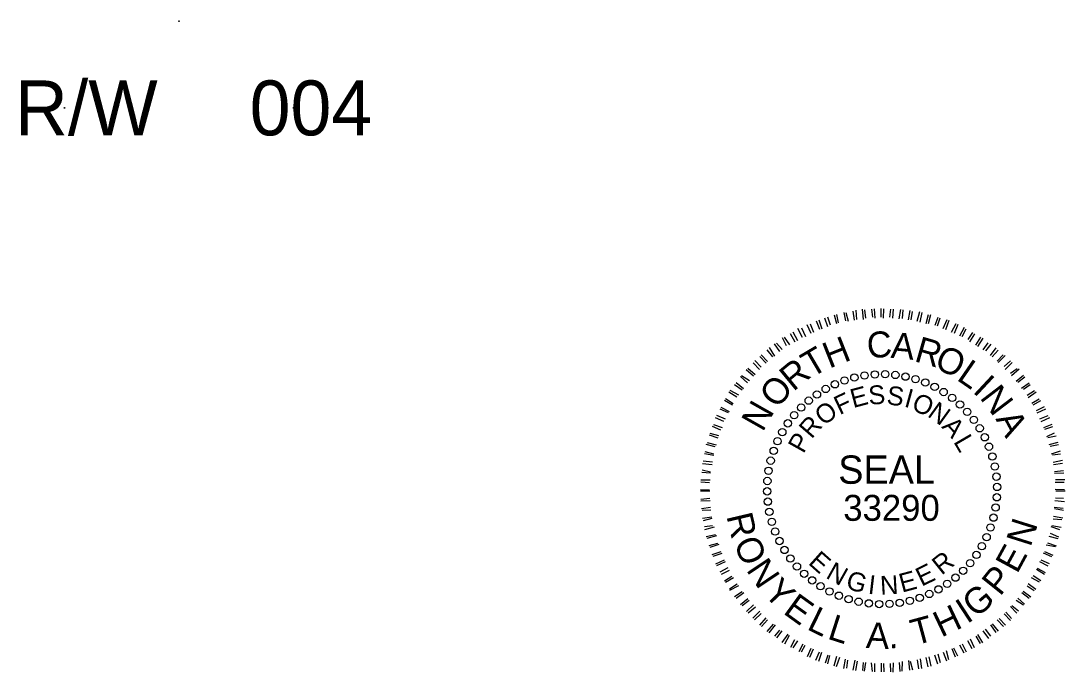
# Model space of a CAD drawing. Extents: x -0.56 to 3.44, y 0 to 1.83.
# Drawn here: x 2.925 to 3.3052, y 1.5473 to 1.7845 of the extents above; entities that cross this region are included whole.
import ezdxf

# ---------------------------------------------------------------- set-up
doc = ezdxf.new("R2010")
doc.units = 0
doc.layers.add('Sheet PE Seal Cell', color=7, linetype='Continuous')
doc.layers.add('Sheet_Title_Block_Text', color=7, linetype='Continuous')

msp = doc.modelspace()

# ---------------------------------------------------------------- linework, layer by layer
at = {"layer": 'Sheet PE Seal Cell'}
for p, q in [((3.21875, 1.67664), (3.21971, 1.67371)), ((3.2221, 1.67407), (3.22124, 1.67723)), ((3.22191, 1.6775), (3.22254, 1.67443)), ((3.22537, 1.67516), (3.22474, 1.67823)), ((3.22532, 1.67826), (3.22618, 1.67509)), ((3.22857, 1.67545), (3.22805, 1.67875)), ((3.22906, 1.67915), (3.22924, 1.67572)), ((3.23177, 1.67574), (3.23145, 1.67951)), ((3.23215, 1.6792), (3.23254, 1.67624)), ((3.23517, 1.6765), (3.23478, 1.67946)), ((3.23569, 1.67962), (3.23588, 1.67619)), ((3.23827, 1.67655), (3.23822, 1.67965)), ((3.23902, 1.67958), (3.23897, 1.67624)), ((3.24137, 1.6766), (3.24178, 1.6795)), ((3.24259, 1.67942), (3.24231, 1.67619)), ((3.24473, 1.67598), (3.24535, 1.67934)), ((3.24616, 1.67927), (3.24587, 1.67604)), ((3.24819, 1.67559), (3.24882, 1.67896)), ((3.24952, 1.67865), (3.249, 1.67552)), ((3.25132, 1.67508), (3.25228, 1.67857)), ((3.25299, 1.67827), (3.25226, 1.67467)), ((3.25458, 1.67422), (3.25544, 1.67748)), ((3.25625, 1.67741), (3.25539, 1.67415)), ((3.25795, 1.6736), (3.25894, 1.67652)), ((3.21276, 1.67057), (3.21133, 1.67371)), ((3.21234, 1.67411), (3.21354, 1.67108)), ((3.2159, 1.67201), (3.2147, 1.67504)), ((3.21548, 1.67554), (3.21657, 1.67227)), ((3.21883, 1.67297), (3.21773, 1.67624)), ((3.25964, 1.67622), (3.25865, 1.67329)), ((3.26077, 1.67237), (3.2622, 1.67567)), ((3.2629, 1.67536), (3.26171, 1.67196)), ((3.26383, 1.67105), (3.26549, 1.67424)), ((3.2662, 1.67393), (3.26477, 1.67064)), ((3.26688, 1.66972), (3.26855, 1.67291)), ((3.20382, 1.66607), (3.20228, 1.66897)), ((3.20296, 1.66924), (3.20483, 1.66647)), ((3.20696, 1.6675), (3.20519, 1.67051)), ((3.20606, 1.67124), (3.20773, 1.668)), ((3.20962, 1.66914), (3.20795, 1.67238)), ((3.2092, 1.67268), (3.21063, 1.66954)), ((3.26905, 1.67213), (3.26759, 1.66941)), ((3.26994, 1.66839), (3.27163, 1.67101)), ((3.27224, 1.67047), (3.27044, 1.66762)), ((3.27269, 1.66636), (3.27449, 1.66921)), ((3.19742, 1.66549), (3.19943, 1.66239)), ((3.20129, 1.6641), (3.19941, 1.66686)), ((3.20009, 1.66713), (3.20216, 1.66483)), ((3.27519, 1.66891), (3.27329, 1.66582)), ((3.27531, 1.66467), (3.27724, 1.66718)), ((3.27818, 1.66677), (3.27625, 1.66426)), ((3.27806, 1.66263), (3.28009, 1.66538)), ((3.19635, 1.65981), (3.19404, 1.66221)), ((3.19458, 1.66281), (3.19689, 1.66041)), ((3.19875, 1.66212), (3.19678, 1.66466)), ((3.28083, 1.66451), (3.27866, 1.66209)), ((3.28047, 1.66047), (3.28264, 1.66288)), ((3.28334, 1.66258), (3.28084, 1.66003)), ((3.18968, 1.65796), (3.19233, 1.65569)), ((3.19395, 1.6575), (3.19164, 1.6599)), ((3.19228, 1.66074), (3.19459, 1.65834)), ((3.28299, 1.65854), (3.28529, 1.66061)), ((3.28589, 1.66007), (3.28339, 1.65753)), ((3.2853, 1.65614), (3.28773, 1.65788)), ((3.28844, 1.65757), (3.2857, 1.65513)), ((3.18962, 1.65267), (3.18697, 1.65494)), ((3.18741, 1.65531), (3.19026, 1.65351)), ((3.19179, 1.65508), (3.18914, 1.65735)), ((3.28741, 1.65327), (3.29004, 1.65548)), ((3.29054, 1.6547), (3.28801, 1.65272)), ((3.18311, 1.64991), (3.1863, 1.64824)), ((3.18759, 1.64992), (3.18484, 1.65195)), ((3.18548, 1.65279), (3.18813, 1.65052)), ((3.28938, 1.65073), (3.29215, 1.6526)), ((3.29242, 1.65193), (3.28999, 1.65019)), ((3.1841, 1.64445), (3.18124, 1.64625)), ((3.18155, 1.64695), (3.1844, 1.64516)), ((3.18566, 1.6474), (3.1828, 1.6492)), ((3.29136, 1.6482), (3.29402, 1.64984)), ((3.29463, 1.64929), (3.29176, 1.64719)), ((3.29313, 1.64519), (3.29579, 1.64683)), ((3.18264, 1.64173), (3.17958, 1.64306)), ((3.17988, 1.64376), (3.18284, 1.6422)), ((3.29629, 1.64606), (3.29339, 1.64452)), ((3.29476, 1.64253), (3.29767, 1.64406)), ((3.29806, 1.64305), (3.29493, 1.64162)), ((3.18097, 1.63854), (3.17791, 1.63987)), ((3.17832, 1.64081), (3.18138, 1.63948)), ((3.29596, 1.63949), (3.299, 1.64069)), ((3.2995, 1.63991), (3.29636, 1.63848)), ((3.17988, 1.63538), (3.17682, 1.63671)), ((3.17713, 1.63741), (3.18029, 1.63632)), ((3.29739, 1.63636), (3.30043, 1.63755)), ((3.30059, 1.63664), (3.29766, 1.63568)), ((3.17889, 1.63246), (3.17573, 1.63355)), ((3.1758, 1.63436), (3.17906, 1.6335)), ((3.29849, 1.63309), (3.30129, 1.63439)), ((3.30192, 1.63327), (3.29886, 1.63265)), ((3.29945, 1.63015), (3.30262, 1.63101)), ((3.17399, 1.6276), (3.17725, 1.62674)), ((3.1778, 1.6293), (3.17454, 1.63015)), ((3.17484, 1.63086), (3.1781, 1.63)), ((3.30279, 1.6301), (3.29972, 1.62948)), ((3.30021, 1.62675), (3.30348, 1.62785)), ((3.17337, 1.62424), (3.17683, 1.62385)), ((3.17728, 1.62617), (3.17392, 1.62679)), ((3.30354, 1.6267), (3.30058, 1.62631)), ((3.30084, 1.62368), (3.30424, 1.62444)), ((3.3043, 1.6233), (3.301, 1.62277)), ((3.17614, 1.61968), (3.17291, 1.61996)), ((3.17308, 1.621), (3.17611, 1.62025)), ((3.17666, 1.62281), (3.17319, 1.62319)), ((3.30472, 1.61976), (3.30129, 1.61958)), ((3.30136, 1.62038), (3.30456, 1.62067)), ((3.17575, 1.61621), (3.17252, 1.6165)), ((3.17259, 1.6173), (3.17593, 1.61726)), ((3.30491, 1.61633), (3.30158, 1.61638)), ((3.30175, 1.61742), (3.30508, 1.61737)), ((3.17244, 1.61374), (3.17577, 1.61369)), ((3.17581, 1.61312), (3.17247, 1.61316)), ((3.23882, 1.61343), (3.23882, 1.61343)), ((3.3016, 1.61385), (3.30493, 1.6138)), ((3.3052, 1.61313), (3.30187, 1.61318)), ((3.17599, 1.60968), (3.17256, 1.6095)), ((3.17263, 1.6103), (3.17583, 1.61059)), ((3.30495, 1.60933), (3.30148, 1.60971)), ((3.30165, 1.61075), (3.30465, 1.61057)), ((3.17281, 1.60687), (3.17612, 1.60739)), ((3.17618, 1.60625), (3.17308, 1.60619)), ((3.30127, 1.60729), (3.3045, 1.607)), ((3.30466, 1.6061), (3.3013, 1.60672)), ((3.17324, 1.60333), (3.17654, 1.60386)), ((3.17657, 1.60328), (3.1734, 1.60242)), ((3.17386, 1.60027), (3.17683, 1.60066)), ((3.30036, 1.6007), (3.30372, 1.60007)), ((3.30404, 1.60273), (3.30081, 1.60302)), ((3.30098, 1.60406), (3.30435, 1.60344)), ((3.17743, 1.60012), (3.17392, 1.59912)), ((3.17452, 1.59663), (3.17792, 1.59739)), ((3.17829, 1.59695), (3.17478, 1.59595)), ((3.29971, 1.5979), (3.30277, 1.59658)), ((3.30332, 1.59913), (3.30016, 1.60023)), ((3.17561, 1.59336), (3.17878, 1.59422)), ((3.17915, 1.59378), (3.17588, 1.59268)), ((3.30171, 1.59285), (3.29834, 1.59347)), ((3.29875, 1.59441), (3.30191, 1.59332)), ((3.3027, 1.59577), (3.29943, 1.59663)), ((3.17671, 1.59009), (3.17998, 1.59118)), ((3.18025, 1.59051), (3.17698, 1.58941)), ((3.30041, 1.58922), (3.29735, 1.59054)), ((3.29766, 1.59125), (3.30072, 1.58992)), ((3.17804, 1.58672), (3.18118, 1.58815)), ((3.18144, 1.58747), (3.17831, 1.58604)), ((3.17958, 1.58381), (3.18248, 1.58535)), ((3.29898, 1.58592), (3.29603, 1.58749)), ((3.29633, 1.58819), (3.29939, 1.58687)), ((3.18288, 1.58434), (3.17998, 1.5828)), ((3.18124, 1.58057), (3.18391, 1.58221)), ((3.18451, 1.58167), (3.18151, 1.5799)), ((3.29586, 1.58001), (3.2929, 1.58158)), ((3.29355, 1.58242), (3.2964, 1.58062)), ((3.29765, 1.58287), (3.2948, 1.58466)), ((3.29501, 1.58514), (3.29796, 1.58357)), ((3.18301, 1.57757), (3.18578, 1.57944)), ((3.18628, 1.57867), (3.18305, 1.577)), ((3.29396, 1.57693), (3.29134, 1.57862)), ((3.29175, 1.57956), (3.2945, 1.57753)), ((3.18489, 1.5748), (3.18766, 1.57667)), ((3.18826, 1.57613), (3.18539, 1.57403)), ((3.18699, 1.57193), (3.18963, 1.57414)), ((3.28802, 1.57419), (3.29043, 1.57203)), ((3.29216, 1.57407), (3.28941, 1.57611)), ((3.28995, 1.57671), (3.2927, 1.57468)), ((3.19013, 1.57336), (3.1876, 1.57139)), ((3.1892, 1.5693), (3.19171, 1.57184)), ((3.19244, 1.57096), (3.18981, 1.56875)), ((3.28763, 1.56878), (3.28531, 1.57118)), ((3.28575, 1.57154), (3.28827, 1.56961)), ((3.29, 1.57166), (3.28738, 1.57336)), ((3.19152, 1.56689), (3.19402, 1.56944)), ((3.19452, 1.56866), (3.19212, 1.56635)), ((3.19406, 1.56439), (3.19633, 1.56704)), ((3.28272, 1.56392), (3.28041, 1.56632)), ((3.28119, 1.56682), (3.2835, 1.56442)), ((3.28536, 1.56613), (3.28305, 1.56853)), ((3.28359, 1.56913), (3.28566, 1.56683)), ((3.19683, 1.56626), (3.19467, 1.56385)), ((3.19671, 1.56212), (3.19898, 1.56477)), ((3.19968, 1.56447), (3.19731, 1.56158)), ((3.19956, 1.56033), (3.20139, 1.56261)), ((3.27612, 1.56287), (3.27809, 1.56034)), ((3.28009, 1.56171), (3.27821, 1.56448)), ((3.27865, 1.56485), (3.28086, 1.56221)), ((3.2021, 1.5623), (3.20017, 1.55979)), ((3.20221, 1.55806), (3.20435, 1.56105)), ((3.20472, 1.56061), (3.20305, 1.55742)), ((3.2054, 1.5564), (3.20686, 1.55912)), ((3.2078, 1.55871), (3.20611, 1.55609)), ((3.27068, 1.55936), (3.27212, 1.55622)), ((3.27445, 1.55773), (3.27281, 1.5604)), ((3.27335, 1.561), (3.27512, 1.55799)), ((3.27745, 1.5595), (3.27534, 1.56237)), ((3.20836, 1.55483), (3.20982, 1.55755)), ((3.21042, 1.55701), (3.20906, 1.55453)), ((3.21145, 1.55293), (3.21277, 1.55599)), ((3.21348, 1.55569), (3.21215, 1.55263)), ((3.26185, 1.55509), (3.26271, 1.55193)), ((3.2653, 1.55275), (3.2641, 1.55579)), ((3.26454, 1.55616), (3.26608, 1.55326)), ((3.26844, 1.55419), (3.2669, 1.55709)), ((3.26768, 1.55759), (3.26922, 1.55469)), ((3.27134, 1.55572), (3.26981, 1.55862)), ((3.2145, 1.55161), (3.21583, 1.55467)), ((3.21654, 1.55436), (3.21544, 1.5512)), ((3.218, 1.55065), (3.21899, 1.55357)), ((3.21946, 1.55337), (3.2187, 1.55034)), ((3.22116, 1.54956), (3.22212, 1.55305)), ((3.22306, 1.55265), (3.22186, 1.54925)), ((3.22465, 1.5486), (3.22528, 1.55196)), ((3.22598, 1.55166), (3.22556, 1.54876)), ((3.22802, 1.54798), (3.22874, 1.55158)), ((3.22945, 1.55127), (3.22883, 1.54791)), ((3.24587, 1.55113), (3.24572, 1.54756)), ((3.24869, 1.54795), (3.24826, 1.55149)), ((3.24873, 1.55128), (3.2496, 1.54811)), ((3.25199, 1.54847), (3.25146, 1.55177)), ((3.25248, 1.55217), (3.2529, 1.54864)), ((3.25539, 1.54923), (3.25463, 1.55264)), ((3.25554, 1.5528), (3.2563, 1.5494)), ((3.2589, 1.55023), (3.2578, 1.5535)), ((3.25881, 1.5539), (3.25967, 1.55073)), ((3.26217, 1.55132), (3.26097, 1.55436)), ((3.23159, 1.54783), (3.23177, 1.55082)), ((3.23257, 1.55075), (3.23206, 1.54762)), ((3.23505, 1.54744), (3.23476, 1.55064)), ((3.23581, 1.55047), (3.23586, 1.54737)), ((3.23838, 1.54739), (3.23833, 1.55049)), ((3.23914, 1.55042), (3.23919, 1.54732)), ((3.24172, 1.54734), (3.24166, 1.55044)), ((3.24257, 1.5506), (3.24252, 1.54727)), ((3.24515, 1.54753), (3.24486, 1.55073))]:
    msp.add_line(p, q, dxfattribs=at)
for centre in [(3.22488, 1.65348), (3.22848, 1.65455), (3.23216, 1.65529), (3.2359, 1.6557), (3.23966, 1.65577), (3.2434, 1.6555), (3.24711, 1.6549), (3.25075, 1.65397), (3.25429, 1.65272), (3.21803, 1.6504), (3.22139, 1.6521), (3.25771, 1.65115), (3.26097, 1.64929), (3.21185, 1.64615), (3.21485, 1.64841), (3.26405, 1.64714), (3.20907, 1.64362), (3.26693, 1.64472), (3.26957, 1.64205), (3.20424, 1.63788), (3.20652, 1.64086), (3.27197, 1.63916), (3.20223, 1.6347), (3.2741, 1.63607), (3.20051, 1.63136), (3.27594, 1.63279), (3.1991, 1.62788), (3.27748, 1.62937), (3.27871, 1.62581), (3.198, 1.62429), (3.27962, 1.62217), (3.19724, 1.62061), (3.28019, 1.61846), (3.1968, 1.61688), (3.28043, 1.61471), (3.19671, 1.61312), (3.28034, 1.61095), (3.19695, 1.60937), (3.2799, 1.60722), (3.19752, 1.60566), (3.27914, 1.60354), (3.19843, 1.60201), (3.27804, 1.59995), (3.19965, 1.59846), (3.27663, 1.59646), (3.2012, 1.59503), (3.20304, 1.59176), (3.27491, 1.59312), (3.20517, 1.58866), (3.2729, 1.58995), (3.20757, 1.58577), (3.26807, 1.5842), (3.27062, 1.58697), (3.21021, 1.58311), (3.21309, 1.58069), (3.26529, 1.58168), (3.21617, 1.57854), (3.21943, 1.57667), (3.25911, 1.57742), (3.26229, 1.57941), (3.22285, 1.57511), (3.22639, 1.57385), (3.23003, 1.57292), (3.24866, 1.57327), (3.25226, 1.57434), (3.25575, 1.57573), (3.23374, 1.57232), (3.23748, 1.57206), (3.24124, 1.57213), (3.24498, 1.57253)]:
    msp.add_circle(centre, 0.00134, dxfattribs=at)
at = {"layer": 'Sheet_Title_Block_Text'}
for centre in [(2.98259, 1.78436), (2.94092, 1.75276), (3.02426, 1.75276)]:
    msp.add_circle(centre, 0.0001, dxfattribs=at)

# ---------------------------------------------------------------- texts
at = {"layer": 'Sheet PE Seal Cell'}
for s, height, rotation, p in [('H', 0.00945, 21.565, (3.21933, 1.65776)), ('C', 0.00945, 4.1195, (3.23334, 1.66155)), ('A', 0.00945, 354.565, (3.24153, 1.66178)), ('R', 0.00945, 344.0819, (3.24996, 1.66058)), ('T', 0.00945, 30.565, (3.21278, 1.65425)), ('O', 0.00945, 335.0819, (3.25713, 1.65828)), ('R', 0.00945, 39.565, (3.20623, 1.64928)), ('L', 0.00945, 325.3965, (3.26537, 1.6539)), ('O', 0.00945, 49.8402, (3.20036, 1.64289)), ('I', 0.00945, 317.0132, (3.27124, 1.64939)), ('E', 0.00687, 14.9192, (3.22803, 1.64342)), ('S', 0.00687, 4.0038, (3.23381, 1.64463)), ('S', 0.00687, 352.848, (3.23999, 1.64482)), ('I', 0.00687, 344.6348, (3.2463, 1.64406)), ('N', 0.00945, 307.3965, (3.2739, 1.64719)), ('N', 0.00945, 60.423, (3.19509, 1.63446)), ('F', 0.00687, 25.3509, (3.22313, 1.64082)), ('O', 0.00687, 335.4243, (3.24886, 1.64308)), ('O', 0.00687, 37.1291, (3.21732, 1.63677)), ('N', 0.00687, 324.2692, (3.25476, 1.64063)), ('R', 0.00687, 49.0287, (3.21289, 1.63195)), ('A', 0.00687, 312.2371, (3.26, 1.63652)), ('A', 0.00945, 298.3965, (3.27976, 1.6395)), ('P', 0.00687, 60.739, (3.20994, 1.62659)), ('L', 0.00687, 300.2563, (3.2644, 1.6312)), ('SEAL', 0.010305, 0.0028, (3.2226, 1.61587)), ('33290', 0.009447, 0.0028, (3.22444, 1.60238)), ('R', 0.00945, 283.2452, (3.18184, 1.60416)), ('N', 0.00945, 72.5046, (3.29262, 1.59257)), ('O', 0.00945, 293.5644, (3.18435, 1.59427)), ('E', 0.00945, 61.4898, (3.28772, 1.58281)), ('E', 0.00687, 318.2926, (3.21138, 1.58683)), ('R', 0.00687, 38.711, (3.26025, 1.58237)), ('N', 0.00945, 303.7838, (3.18889, 1.58451)), ('N', 0.00687, 330.7412, (3.21774, 1.58174)), ('E', 0.00687, 26.1459, (3.25296, 1.57833)), ('P', 0.00945, 51.2741, (3.28152, 1.57463)), ('Y', 0.00945, 314.4613, (3.19505, 1.57581)), ('G', 0.00687, 343.6968, (3.22499, 1.57785)), ('I', 0.00687, 353.2466, (3.23323, 1.57584)), ('N', 0.00687, 3.1977, (3.23803, 1.5754)), ('E', 0.00687, 14.8978, (3.24579, 1.57619)), ('G', 0.00945, 40.1342, (3.27278, 1.56674)), ('E', 0.00945, 324.1361, (3.20219, 1.56885)), ('L', 0.00945, 333.9963, (3.21081, 1.56303)), ('H', 0.00945, 25.3568, (3.26011, 1.5598)), ('I', 0.00945, 33.2125, (3.26948, 1.56468)), ('L', 0.00945, 342.2461, (3.21833, 1.55953)), ('T', 0.00945, 15.1355, (3.25049, 1.55693)), ('A', 0.00945, 357.5853, (3.23256, 1.55606)), ('.', 0.00945, 3.2238, (3.24109, 1.55588))]:
    msp.add_text(s, height=height, rotation=rotation, dxfattribs=at).set_placement(p)
at = {"layer": 'Sheet_Title_Block_Text'}
for s, p in [('R/W', (2.92284, 1.74276)), ('004', (3.00833, 1.74276))]:
    msp.add_text(s, height=0.02, dxfattribs=at).set_placement(p)

doc.saveas('drawing.dxf')
